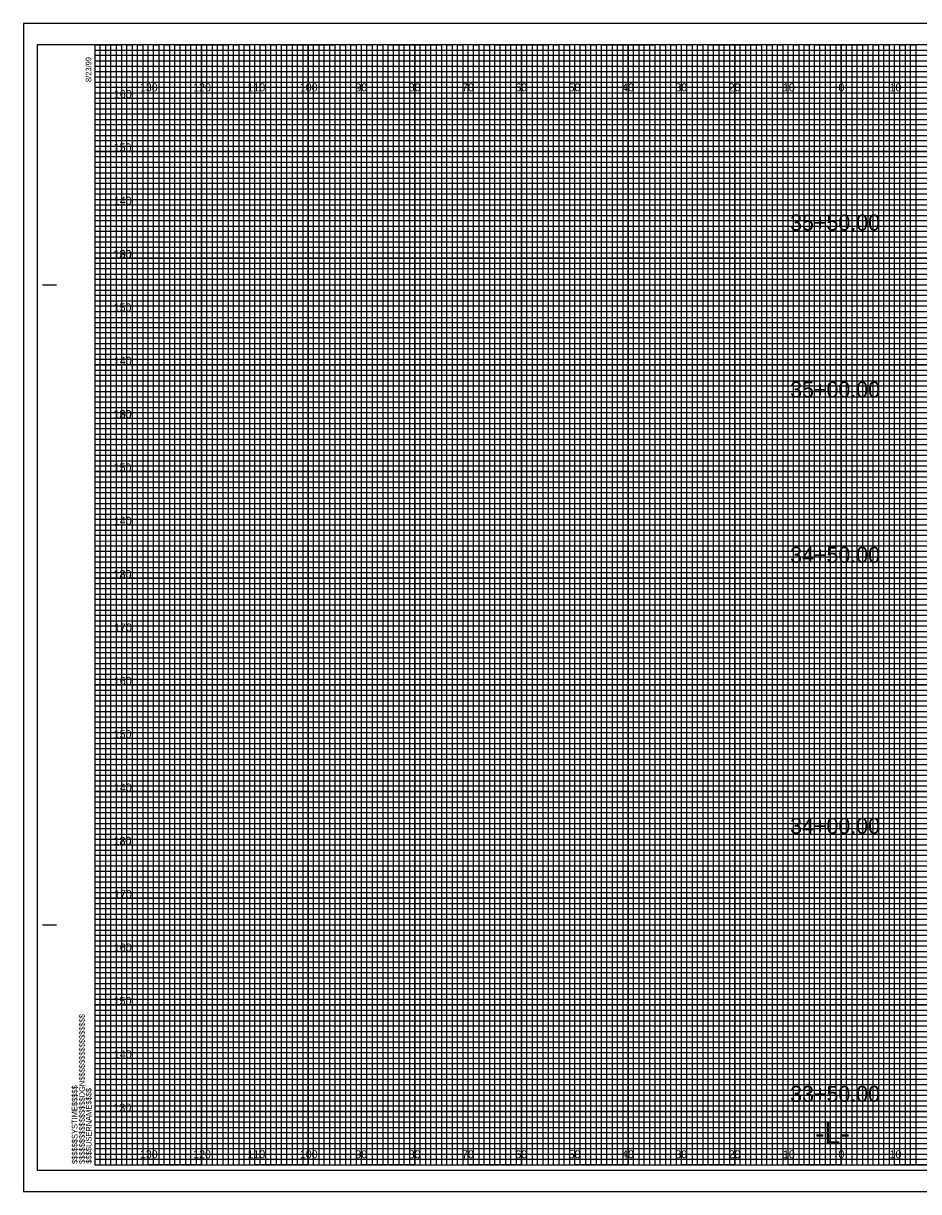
# Model space of a CAD drawing. Extents: x -13 to 323, y -5 to 214.
# Drawn here: x -13.4 to 154.5, y -5 to 214 of the extents above; entities that cross this region are included whole.
import ezdxf

# ---------------------------------------------------------------- set-up
doc = ezdxf.new("R2010")
doc.units = 0
for name, color, linetype in [('Exist Cross Section Cell', 7, 'Continuous'), ('Exist XS Center Line Elevation Label', 7, 'Continuous'), ('Exist XS Ground Line', 7, 'Continuous'), ('Prop CMT Ditch DDE', 7, 'Continuous'), ('Prop CMT Guardrail Graphics', 7, 'Continuous'), ('Prop CMT Pvmt Course 1', 7, 'Continuous'), ('Prop CMT Pvmt Course 2', 7, 'Continuous'), ('Prop CMT Pvmt Surface', 7, 'Continuous'), ('Prop CMT Pvmt Surface Overlay', 7, 'Continuous'), ('Prop CMT Pvmt Surface Shoulder', 7, 'Continuous'), ('Prop CMT Shld Paved Course 1', 7, 'Continuous'), ('Prop CMT Shld Paved Course 2', 7, 'Continuous'), ('Scratch_Level_9', 7, 'Continuous')]:
    doc.layers.add(name, color=color, linetype=linetype)

msp = doc.modelspace()

# ---------------------------------------------------------------- linework, layer by layer
at = {"layer": 'Exist XS Center Line Elevation Label'}
for p, q in [((0, 209), (260, 209)), ((260, 207.98), (0, 207.98)), ((0, 207.98), (0, 207)), ((0, 207), (260, 207)), ((260, 205.89), (0, 205.89)), ((0, 205.89), (0, 204)), ((0, 204), (320, 204))]:
    msp.add_line(p, q, dxfattribs=at)
for points in [[(0, 203), (270, 203), (320, 203), (320, 202), (0, 202)], [(0, 201), (320, 201), (320, 199), (0, 199)], [(0, 198), (320, 198), (320, 197), (0, 196.98)], [(0, 196), (320, 196), (320, 194), (0, 194)], [(0, 193), (320, 193), (320, 192), (0, 192)], [(0, 191), (320, 191), (320, 189), (0, 189)], [(0, 188), (320, 188), (320, 187), (0, 187)], [(0, 186), (320, 186), (320, 184), (0, 184)], [(0, 183), (320, 183), (320, 182), (0, 182)], [(0, 181), (320, 181), (320, 179), (0, 179)], [(0, 178), (320, 178), (320, 177), (0, 177)], [(0, 176), (320, 176), (320, 173.95), (320, 173), (320, 172), (0, 172)], [(0, 174), (320, 174), (320, 173), (0, 173)], [(0, 171), (320, 171), (320, 169), (0, 169.03)], [(0, 169.03), (320, 169), (320, 168), (0, 168)], [(0, 167), (320, 167), (320, 166), (0, 166)], [(0, 164), (320, 164), (320, 163), (0, 163)], [(0, 162), (320, 162), (320, 161), (0, 161)], [(-0.07, 158.89), (320, 158.89), (320, 157.88), (-0.07, 157.88)], [(0, 157), (320, 157), (320, 156), (0, 156)], [(0, 154), (320, 154), (320, 153), (0, 153)], [(0, 152), (320, 152), (320, 151), (0, 151)], [(0, 149), (320, 149), (320, 148), (0, 148)], [(0, 147), (320, 147), (320, 146), (0, 146)], [(0, 144), (320, 144), (320, 143), (0, 143)], [(0, 142), (320, 142), (320, 141), (0, 141)], [(0, 139), (320, 139), (319.99, 137.98), (0, 138)], [(0, 137), (320, 137), (320, 136), (0, 136)], [(0, 134), (320, 134), (320, 133), (0, 133)], [(0, 132), (320, 132), (320, 131), (0, 131)], [(0, 129), (320, 129), (320, 128), (0, 128)], [(0, 127), (320, 127), (320, 126), (0, 126)], [(0, 124), (320, 124), (320, 123), (0, 123)], [(0, 122), (320, 122), (320, 121), (0, 121)], [(0, 119), (320, 119), (320, 118), (0, 118)], [(0, 116.99), (320.07, 116.91), (320, 116), (0, 116)], [(0, 114), (320, 114), (320, 113), (0, 113)], [(0, 112), (320, 112), (320, 111), (0, 111)], [(0, 109), (320, 109), (320, 108), (0, 108)], [(0, 107), (320, 107), (320, 106), (0, 106)], [(0, 104), (320, 104), (320, 103), (0, 103)], [(0, 102), (320, 102), (320, 101), (0, 101)], [(0, 99), (320, 99), (320, 98), (0, 98)], [(0, 97), (320, 97), (320, 96), (0, 96)], [(0, 94), (320, 94), (320, 93), (0, 93)], [(0, 92), (320, 92), (320, 91), (0, 91)], [(0, 89), (320, 89), (320, 88), (0, 88)], [(0, 87), (320, 87), (320, 86), (0, 86)], [(0, 84), (320, 84), (320, 83), (0, 83)], [(0, 82), (320, 82), (320, 81), (0, 81)], [(0, 79), (320, 79), (319.99, 77.98), (0, 78)], [(0, 77), (320, 77), (320, 76), (0, 76)], [(0, 74), (320, 74), (320, 73), (0, 73)], [(0, 72), (320, 72), (320, 71), (0, 71)], [(0, 69), (320, 69), (320, 68), (0, 68)], [(0, 67), (320, 67), (320, 66), (0, 66)], [(0, 64), (320, 64), (320, 63), (0, 63)], [(0, 62), (320, 62), (320, 61), (0, 61)], [(0, 59), (320, 59), (320, 58), (0, 58)], [(0, 56.99), (320.07, 56.91), (320, 56), (0, 56)], [(0, 54), (320, 54), (320, 53), (0, 53)], [(0, 52), (320, 52), (320, 51), (0, 51)], [(0, 49), (320, 49), (320, 48), (0, 48)], [(0, 47), (320, 47), (320, 46), (0, 46)], [(0, 44), (320, 44), (320, 43), (0, 43)], [(0, 42), (320, 42), (320, 41), (0, 41)], [(0, 39), (320, 39), (320, 38), (0, 38)], [(0, 37), (320, 37), (320, 36), (0, 36)], [(0, 34), (320, 34), (320, 33), (0, 33)], [(0, 32), (320, 32), (320, 31), (0, 31)], [(0, 29), (320, 29), (320, 28), (0, 28)], [(0, 27), (320, 27), (320, 26), (0, 26)], [(0, 24), (320, 24), (320, 23), (0, 23)], [(0, 22), (320, 22), (320, 21), (0, 21)], [(0, 19), (320, 19), (320, 18), (0, 18)], [(0, 17), (320, 17), (320, 16), (0, 16)], [(0, 14), (320, 14), (320, 13), (0, 13)], [(0, 12), (320, 12), (320, 11), (0, 11)], [(0, 9), (320, 9), (320, 8), (0, 8)], [(0, 7), (320, 7), (320, 6), (0, 6)], [(0, 4), (320, 4), (320, 3), (0, 3)], [(0, 2), (320, 2), (320, 1), (0, 1)]]:
    msp.add_lwpolyline(points, dxfattribs=at)
at = {"layer": 'Exist XS Ground Line'}
for points in [[(0, 210), (5, 210), (5, 0), (15, 0), (15, 210), (25, 210), (25, 0), (35, 0), (35, 210), (45, 210), (45, 0), (55, 0), (55, 210), (65, 210), (65, 0), (75, 0), (75, 210), (85, 210), (85, 0), (95, 0), (95, 210), (105, 210), (105, 0), (115, 0), (115, 210), (125, 210), (125, 0), (135, 0), (135, 210), (145, 210), (145, 0), (155, 0)], [(0, 205), (275, 205)], [(0, 185), (320, 185), (320, 195), (0, 195)], [(0, 165), (320, 165), (320, 175), (0, 175)], [(0, 145), (320, 145), (320, 155), (0, 155)], [(0, 125), (320, 125), (320, 135), (0, 135)], [(0, 105), (320, 105), (320, 115), (0, 115)], [(0, 85), (320, 85), (320, 95), (0, 95)], [(0, 65), (320, 65), (320, 75), (0, 75)], [(0, 45), (320, 45), (320, 55), (0, 55)], [(0, 25), (320, 25), (320, 35), (0, 35)], [(0, 5), (320, 5), (320, 15), (0, 15)]]:
    msp.add_lwpolyline(points, dxfattribs=at)
at = {"layer": 'Prop CMT Guardrail Graphics'}
msp.add_lwpolyline([(-10.8, -1), (322.4, -1), (322.4, 210), (-10.8, 210)], close=True, dxfattribs=at)
at = {"layer": 'Prop CMT Pvmt Course 1'}
for p, q in [((323.3, 214), (-13.4, 214)), ((-13.4, 214), (-13.4, -5)), ((-13.4, -5), (323.3, -5))]:
    msp.add_line(p, q, dxfattribs=at)
at = {"layer": 'Prop CMT Pvmt Surface'}
msp.add_lwpolyline([(-13.4, -5), (323.3, -5), (323.3, 214), (-13.4, 214)], close=True, dxfattribs=at)
at = {"layer": 'Prop CMT Pvmt Surface Shoulder'}
for p, q in [((10, 0), (10, 210)), ((20, 0), (20, 210)), ((30, 0), (30, 210)), ((40, 0), (40, 210)), ((50, 0), (50, 210)), ((60, 0), (60, 210)), ((70, 0), (70, 210)), ((80, 0), (80, 210)), ((90, 0), (90, 210)), ((100, 0), (100, 210)), ((110, 0), (110, 210)), ((120, 0), (120, 210)), ((130, 0), (130, 210)), ((140, 0), (140, 210)), ((150, 0), (150, 210)), ((0, 200), (320, 200)), ((0, 190), (320, 190)), ((0, 180), (320, 180)), ((0, 170), (320, 170)), ((0, 160), (320, 160)), ((0, 150), (320, 150)), ((0, 140), (320, 140)), ((0, 130), (320, 130)), ((0, 120), (320, 120)), ((0, 110), (320, 110)), ((0, 100), (320, 100)), ((0, 90), (320, 90)), ((0, 80), (320, 80)), ((0, 70), (320, 70)), ((0, 60), (320, 60)), ((0, 50), (320, 50)), ((0, 40), (320, 40)), ((0, 30), (320, 30)), ((0, 20), (320, 20)), ((0, 10), (320, 10))]:
    msp.add_line(p, q, dxfattribs=at)
at = {"layer": 'Prop CMT Shld Paved Course 1'}
for p, q in [((-9.8, 165), (-7.3, 165)), ((-9.7, 165), (-7.2, 165)), ((-9.8, 45), (-7.3, 45)), ((-9.7, 45), (-7.2, 45)), ((0, 0), (0, 0)), ((0, 0), (0, 0)), ((0, 0), (0, 0)), ((0, 0), (0, 0)), ((0, 0), (0, 0)), ((0, 0), (0, 0)), ((0, 0), (0, 0))]:
    msp.add_line(p, q, dxfattribs=at)
msp.add_lwpolyline([(320, 210), (0, 210), (0, 0), (320, 0)], close=True, dxfattribs=at)
at = {"layer": 'Prop CMT Shld Paved Course 2'}
for points in [[(0, 0), (1, 0), (1, 210), (2, 210), (2, 0)], [(2, 0), (3, 0), (3, 210), (4, 210), (4, 0)], [(5, 0), (6, 0), (6, 210), (7, 210), (7, 0)], [(7, 0), (8, 0), (8, 210), (9, 210), (9, 0)], [(10, 0), (11, 0), (11, 210), (12, 210), (12, 0)], [(12, 0), (13, 0), (13, 210), (14, 210), (14, 0)], [(15, 0), (16, 0), (16, 210), (17, 210), (17, 0)], [(17, 0), (18, 0), (18, 210), (19, 210), (19, 0)], [(20, 0), (21, 0), (21, 210), (22, 210), (22, 0)], [(22, 0), (23, 0), (23, 210), (24, 210), (24, 0)], [(25, 0), (26, 0), (26, 210), (27, 210), (27, 0)], [(27, 0), (28, 0), (28, 210), (29, 210), (29, 0)], [(30, 0), (31, 0), (31, 210), (32, 210), (32, 0)], [(32, 0), (33, 0), (33, 210), (34, 210), (34, 0)], [(35, 0), (36, 0), (36, 210), (37, 210), (37, 0)], [(37, 0), (38, 0), (38, 210), (39, 210), (39, 0)], [(40, 0), (41, 0), (41, 210), (42, 210), (42, 0)], [(42, 0), (43, 0), (43, 210), (44, 210), (44, 0)], [(45, 0), (46, 0), (46, 210), (47, 210), (47, 0)], [(47, 0), (48, 0), (48, 210), (49, 210), (49, 0)], [(50, 0), (51, 0), (51, 210), (52, 210), (52, 0)], [(52, 0), (53, 0), (53, 210), (54, 210), (54, 0)], [(55, 0), (56, 0), (56, 210), (57, 210), (57, 0)], [(57, 0), (58, 0), (58, 210), (59, 210), (59, 0)], [(60, 0), (61, 0), (61, 210), (62, 210), (62, 0)], [(62, 0), (63, 0), (63, 210), (64, 210), (64, 0)], [(65, 0), (66, 0), (66, 210), (67, 210), (67, 0)], [(67, 0), (68, 0), (68, 210), (69, 210), (69, 0)], [(70, 0), (71, 0), (71, 210), (72, 210), (72, 0)], [(72, 0), (73, 0), (73, 210), (74, 210), (74, 0)], [(75, 0), (76, 0), (76, 210), (77, 210), (77, 0)], [(77, 0), (78, 0), (78, 210), (79, 210), (79, 0)], [(80, 0), (81, 0), (81, 210), (82, 210), (82, 0)], [(82, 0), (83, 0), (83, 210), (84, 210), (84, 0)], [(85, 0), (86, 0), (86, 210), (87, 210), (87, 0)], [(87, 0), (88, 0), (88, 210), (89, 210), (89, 0)], [(90, 0), (91, 0), (91, 210), (92, 210), (92, 0)], [(92, 0), (93, 0), (93, 210), (94, 210), (94, 0)], [(95, 0), (96, 0), (96, 210), (97, 210), (97, 0)], [(97, 0), (98, 0), (98, 210), (99, 210), (99, 0)], [(100, 0), (101, 0), (101, 210), (102, 210), (102, 0)], [(102, 0), (103, 0), (103, 210), (104, 210), (104, 0)], [(105, 0), (106, 0), (106, 210), (107, 210), (107, 0)], [(107, 0), (108, 0), (108, 210), (109, 210), (109, 0)], [(110, 0), (111, 0), (111, 210), (112, 210), (112, 0)], [(112, 0), (113, 0), (113, 210), (114, 210), (114, 0)], [(115, 0), (116, 0), (116, 210), (117, 210), (117, 0)], [(117, 0), (118, 0), (118, 210), (119, 210), (119, 0)], [(120, 0), (121, 0), (121, 210), (122, 210), (122, 0)], [(122, 0), (123, 0), (123, 210), (124, 210), (124, 0)], [(125, 0), (126, 0), (126, 210), (127, 210), (127, 0)], [(127, 0), (128, 0), (128, 210), (129, 210), (129, 0)], [(130, 0), (131, 0), (131, 210), (132, 210), (132, 0)], [(132, 0), (133, 0), (133, 210), (134, 210), (134, 0)], [(135, 0), (136, 0), (136, 210), (137, 210), (137, 0)], [(137, 0), (138, 0), (138, 210), (139, 210), (139, 0)], [(140, 0), (141, 0), (141, 210), (142, 210), (142, 0)], [(142, 0), (143, 0), (143, 210), (144, 210), (144, 0)], [(145, 0), (146, 0), (146, 210), (147, 210), (147, 0)], [(147, 0), (148, 0), (148, 210), (149, 210), (149, 0)], [(150, 0), (151, 0), (151, 210), (152, 210), (152, 0)], [(152, 0), (153, 0), (153, 210), (154, 210), (154, 0)]]:
    msp.add_lwpolyline(points, dxfattribs=at)
at = {"layer": 'Scratch_Level_9'}
for p, q in [((10, 210), (0, 210)), ((10, 0), (10, 210)), ((30, 210), (20, 210)), ((20, 210), (20, 0)), ((30, 0), (30, 210)), ((50, 210), (40, 210)), ((40, 210), (40, 0)), ((50, 0), (50, 210)), ((70, 210), (60, 210)), ((60, 210), (60, 0)), ((70, 0), (70, 210)), ((90, 210), (80, 210)), ((80, 210), (80, 0)), ((90, 0), (90, 210)), ((110, 210), (100, 210)), ((100, 210), (100, 0)), ((110, 0), (110, 210)), ((130, 210), (120, 210)), ((120, 210), (120, 0)), ((130, 0), (130, 210)), ((150, 210), (140, 210)), ((140, 210), (140, 0)), ((150, 0), (150, 210)), ((20, 0), (10, 0)), ((40, 0), (30, 0)), ((60, 0), (50, 0)), ((80, 0), (70, 0)), ((100, 0), (90, 0)), ((120, 0), (110, 0)), ((140, 0), (130, 0)), ((160, 0), (150, 0))]:
    msp.add_line(p, q, dxfattribs=at)
for points in [[(0, 200), (320, 200), (320, 190), (0, 190)], [(0, 180), (320, 180), (320, 170), (0, 170)], [(0, 160), (320, 160), (320, 150), (0, 150)], [(0, 140), (320, 140), (320, 130), (0, 130)], [(0, 120), (320, 120), (320, 110), (0, 110)], [(0, 100), (320, 100), (320, 90), (0, 90)], [(0, 80), (320, 80), (320, 70), (0, 70)], [(0, 60), (320, 60), (320, 50), (0, 50)], [(0, 40), (320, 40), (320, 30), (0, 30)], [(0, 20), (320, 20), (320, 10), (0, 10)]]:
    msp.add_lwpolyline(points, dxfattribs=at)

# ---------------------------------------------------------------- texts
at = {"layer": 'Exist Cross Section Cell'}
for s, p in [('130', (8.44, 201.25)), ('120', (18.44, 201.25)), ('110', (28.62, 201.25)), ('100', (38.44, 201.25)), ('90', (48.86, 201.25)), ('80', (58.86, 201.25)), ('70', (68.86, 201.25)), ('60', (78.86, 201.25)), ('50', (88.86, 201.25)), ('40', (98.86, 201.25)), ('30', (108.86, 201.25)), ('20', (118.86, 201.25)), ('10', (129.04, 201.25)), ('0', (139.45, 201.25)), ('0', (139.45, 201.25)), ('10', (149.04, 201.25)), ('130', (8.44, 1.25)), ('120', (18.44, 1.25)), ('110', (28.62, 1.25)), ('100', (38.44, 1.25)), ('90', (48.86, 1.25)), ('80', (58.86, 1.25)), ('70', (68.86, 1.25)), ('60', (78.86, 1.25)), ('50', (88.86, 1.25)), ('40', (98.86, 1.25)), ('30', (108.86, 1.25)), ('20', (118.86, 1.25)), ('10', (129.04, 1.25)), ('0', (139.45, 1.25)), ('0', (139.45, 1.25)), ('10', (149.04, 1.25))]:
    msp.add_text(s, height=1.5, dxfattribs=at).set_placement(p)
at = {"layer": 'Prop CMT Ditch DDE'}
msp.add_text('-L-', height=4, dxfattribs=at).set_placement((135.06, 4))
at = {"layer": 'Prop CMT Pvmt Course 2'}
for s, p in [('160', (3.57, 200)), ('150', (3.52, 190)), ('140', (3.57, 180)), ('130', (3.49, 170)), ('160', (3.57, 170)), ('150', (3.52, 160)), ('140', (3.57, 150)), ('130', (3.49, 140)), ('160', (3.57, 140)), ('150', (3.52, 130)), ('140', (3.57, 120)), ('130', (3.49, 110)), ('180', (3.55, 110)), ('170', (3.61, 100)), ('160', (3.57, 90)), ('150', (3.52, 80)), ('140', (3.57, 70)), ('130', (3.49, 60)), ('180', (3.55, 60)), ('170', (3.61, 50)), ('160', (3.57, 40)), ('150', (3.52, 30)), ('140', (3.57, 20)), ('130', (3.49, 10))]:
    msp.add_text(s, height=1.5, dxfattribs=at).set_placement(p)
at = {"layer": 'Prop CMT Pvmt Surface Overlay'}
for s, p in [('35+50.00', (130.41, 175.16)), ('35+00.00', (130.41, 143.86)), ('34+50.00', (130.41, 112.88)), ('34+00.00', (130.41, 62.08)), ('33+50.00', (130.41, 11.83))]:
    msp.add_text(s, height=3, dxfattribs=at).set_placement(p)
at = {"layer": 'Prop CMT Shld Paved Course 1'}
for s, p in [('8/23/99', (-0.65, 203)), ('$$$$$$$$$$$$$$$$DGN$$$$$$$$$$$$$$$$', (-1.88, 0.18)), ('$$$$$$SYSTIME$$$$$', (-3.26, 0.18)), ('$$$$USERNAME$$$$', (-0.62, 0.23))]:
    msp.add_text(s, height=1.05, rotation=90, dxfattribs=at).set_placement(p)

doc.saveas('drawing.dxf')
